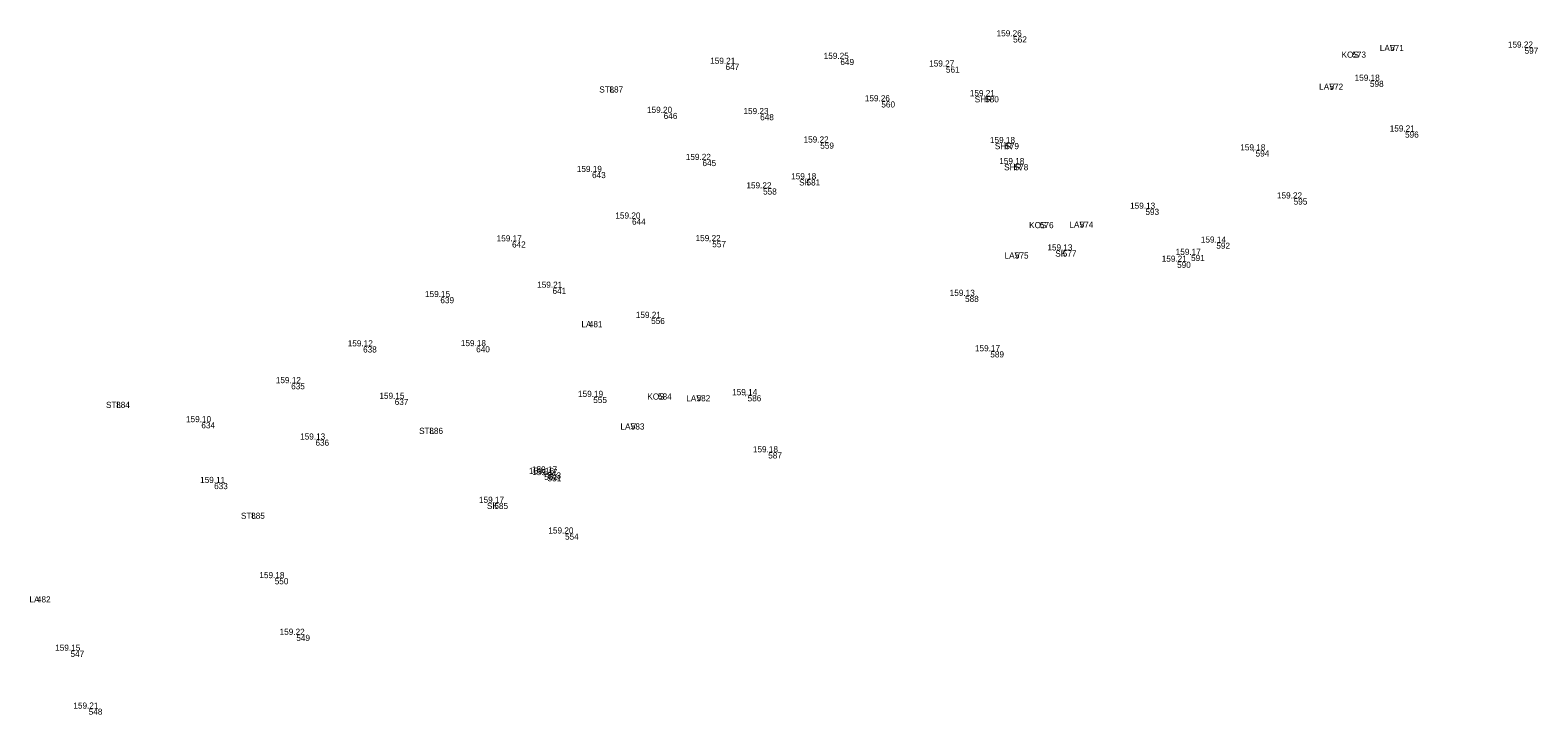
# Model space of a CAD drawing. Extents: x -583198 to -582878, y -1211024 to -1210637.
# Drawn here: x -582990.8 to -582929.4, y -1210859.4 to -1210831.4 of the extents above; entities that cross this region are included whole.
import ezdxf

# ---------------------------------------------------------------- set-up
doc = ezdxf.new("R2010")
doc.units = 0
for name, color, linetype in [('1   Kódy', 7, 'Continuous'), ('4   Body podrobné', 7, 'Continuous'), ('5   Body podrobné - čísla', 7, 'Continuous'), ('6   Body podrobné - výšky', 7, 'Continuous')]:
    doc.layers.add(name, color=color, linetype=linetype)

msp = doc.modelspace()

# ---------------------------------------------------------------- linework, layer by layer
at = {"layer": '4   Body podrobné'}
for p, q in [((-582950.84, -1210831.69), (-582950.839, -1210831.69)), ((-582957.88, -1210832.61), (-582957.879, -1210832.61)), ((-582937.02, -1210832.31), (-582937.019, -1210832.31)), ((-582935.48, -1210832.04), (-582935.479, -1210832.04)), ((-582930, -1210832.15), (-582929.999, -1210832.15)), ((-582962.56, -1210832.81), (-582962.559, -1210832.81)), ((-582953.58, -1210832.92), (-582953.579, -1210832.92)), ((-582967.29, -1210833.73), (-582967.289, -1210833.73)), ((-582937.95, -1210833.62), (-582937.949, -1210833.62)), ((-582936.3, -1210833.5), (-582936.299, -1210833.5)), ((-582956.21, -1210834.34), (-582956.209, -1210834.34)), ((-582951.98, -1210834.13), (-582951.979, -1210834.13)), ((-582965.08, -1210834.81), (-582965.079, -1210834.81)), ((-582961.15, -1210834.86), (-582961.149, -1210834.86)), ((-582934.87, -1210835.57), (-582934.869, -1210835.57)), ((-582958.7, -1210836.02), (-582958.699, -1210836.02)), ((-582951.16, -1210836.04), (-582951.159, -1210836.04)), ((-582963.5, -1210836.73), (-582963.499, -1210836.73)), ((-582950.78, -1210836.9), (-582950.779, -1210836.9)), ((-582940.96, -1210836.34), (-582940.959, -1210836.34)), ((-582968, -1210837.22), (-582967.999, -1210837.22)), ((-582959.26, -1210837.52), (-582959.259, -1210837.52)), ((-582961.03, -1210837.89), (-582961.029, -1210837.89)), ((-582945.45, -1210838.72), (-582945.449, -1210838.72)), ((-582939.41, -1210838.3), (-582939.409, -1210838.3)), ((-582966.37, -1210839.12), (-582966.369, -1210839.12)), ((-582949.75, -1210839.26), (-582949.749, -1210839.26)), ((-582948.13, -1210839.24), (-582948.129, -1210839.24)), ((-582971.26, -1210840.05), (-582971.259, -1210840.05)), ((-582963.1, -1210840.04), (-582963.099, -1210840.04)), ((-582950.77, -1210840.5), (-582950.769, -1210840.5)), ((-582948.82, -1210840.42), (-582948.819, -1210840.42)), ((-582943.59, -1210840.6), (-582943.589, -1210840.6)), ((-582942.56, -1210840.1), (-582942.559, -1210840.1)), ((-582944.16, -1210840.88), (-582944.159, -1210840.88)), ((-582974.18, -1210842.32), (-582974.179, -1210842.32)), ((-582969.61, -1210841.94), (-582969.609, -1210841.94)), ((-582952.8, -1210842.27), (-582952.799, -1210842.27)), ((-582968.13, -1210843.3), (-582968.129, -1210843.3)), ((-582965.59, -1210843.17), (-582965.589, -1210843.17)), ((-582977.33, -1210844.33), (-582977.329, -1210844.33)), ((-582972.72, -1210844.32), (-582972.719, -1210844.32)), ((-582951.77, -1210844.53), (-582951.769, -1210844.53)), ((-582980.26, -1210845.83), (-582980.259, -1210845.83)), ((-582987.39, -1210846.59), (-582987.389, -1210846.59)), ((-582976.04, -1210846.47), (-582976.039, -1210846.47)), ((-582967.95, -1210846.39), (-582967.949, -1210846.39)), ((-582965.31, -1210846.25), (-582965.309, -1210846.25)), ((-582963.74, -1210846.32), (-582963.739, -1210846.32)), ((-582961.66, -1210846.32), (-582961.659, -1210846.32)), ((-582983.92, -1210847.42), (-582983.919, -1210847.42)), ((-582974.63, -1210847.65), (-582974.629, -1210847.65)), ((-582966.42, -1210847.47), (-582966.419, -1210847.47)), ((-582979.27, -1210848.13), (-582979.269, -1210848.13)), ((-582960.82, -1210848.65), (-582960.819, -1210848.65)), ((-582969.95, -1210849.53), (-582969.949, -1210849.53)), ((-582969.82, -1210849.47), (-582969.819, -1210849.47)), ((-582969.81, -1210849.58), (-582969.809, -1210849.58)), ((-582983.4, -1210849.9), (-582983.399, -1210849.9)), ((-582971.98, -1210850.71), (-582971.979, -1210850.71)), ((-582981.89, -1210851.11), (-582981.889, -1210851.11)), ((-582969.1, -1210851.96), (-582969.099, -1210851.96)), ((-582980.93, -1210853.78), (-582980.929, -1210853.78)), ((-582990.62, -1210854.52), (-582990.619, -1210854.52)), ((-582980.05, -1210856.09), (-582980.049, -1210856.09)), ((-582989.25, -1210856.74), (-582989.249, -1210856.74)), ((-582988.51, -1210859.1), (-582988.509, -1210859.1))]:
    msp.add_line(p, q, dxfattribs=at)

# ---------------------------------------------------------------- texts
at = {"layer": '1   Kódy'}
for s, p in [('KOS', (-582937.365, -1210832.56)), ('LAV', (-582935.808, -1210832.29)), ('STL', (-582967.612, -1210833.98)), ('LAV', (-582938.278, -1210833.87)), ('SHR', (-582952.314, -1210834.38)), ('SHR', (-582951.494, -1210836.29)), ('SHR', (-582951.114, -1210837.15)), ('SK', (-582959.469, -1210837.77)), ('KOS', (-582950.095, -1210839.51)), ('LAV', (-582948.458, -1210839.49)), ('LAV', (-582951.098, -1210840.75)), ('SK', (-582949.029, -1210840.67)), ('LA', (-582968.34, -1210843.55)), ('STL', (-582987.712, -1210846.84)), ('KOS', (-582965.655, -1210846.5)), ('LAV', (-582964.068, -1210846.57)), ('STL', (-582974.952, -1210847.9)), ('LAV', (-582966.748, -1210847.72)), ('SK', (-582972.189, -1210850.96)), ('STL', (-582982.212, -1210851.36)), ('LA', (-582990.83, -1210854.77))]:
    msp.add_text(s, height=0.25, dxfattribs=at).set_placement(p)
at = {"layer": '5   Body podrobné - čísla'}
for s, p in [(' 562', (-582950.84, -1210831.94)), (' 649', (-582957.88, -1210832.86)), (' 573', (-582937.02, -1210832.56)), (' 571', (-582935.48, -1210832.29)), (' 597', (-582930, -1210832.4)), (' 647', (-582962.56, -1210833.06)), (' 561', (-582953.58, -1210833.17)), (' 887', (-582967.29, -1210833.98)), (' 572', (-582937.95, -1210833.87)), (' 598', (-582936.3, -1210833.75)), (' 560', (-582956.21, -1210834.59)), (' 580', (-582951.98, -1210834.38)), (' 646', (-582965.08, -1210835.06)), (' 648', (-582961.15, -1210835.11)), (' 596', (-582934.87, -1210835.82)), (' 559', (-582958.7, -1210836.27)), (' 579', (-582951.16, -1210836.29)), (' 645', (-582963.5, -1210836.98)), (' 578', (-582950.78, -1210837.15)), (' 594', (-582940.96, -1210836.59)), (' 643', (-582968, -1210837.47)), (' 581', (-582959.26, -1210837.77)), (' 558', (-582961.03, -1210838.14)), (' 593', (-582945.45, -1210838.97)), (' 595', (-582939.41, -1210838.55)), (' 644', (-582966.37, -1210839.37)), (' 576', (-582949.75, -1210839.51)), (' 574', (-582948.13, -1210839.49)), (' 642', (-582971.26, -1210840.3)), (' 557', (-582963.1, -1210840.29)), (' 575', (-582950.77, -1210840.75)), (' 577', (-582948.82, -1210840.67)), (' 591', (-582943.59, -1210840.85)), (' 592', (-582942.56, -1210840.35)), (' 590', (-582944.16, -1210841.13)), (' 639', (-582974.18, -1210842.57)), (' 641', (-582969.61, -1210842.19)), (' 588', (-582952.8, -1210842.52)), (' 481', (-582968.13, -1210843.55)), (' 556', (-582965.59, -1210843.42)), (' 640', (-582972.72, -1210844.57)), (' 638', (-582977.33, -1210844.58)), (' 589', (-582951.77, -1210844.78)), (' 635', (-582980.26, -1210846.08)), (' 884', (-582987.39, -1210846.84)), (' 637', (-582976.04, -1210846.72)), (' 555', (-582967.95, -1210846.64)), (' 584', (-582965.31, -1210846.5)), (' 582', (-582963.74, -1210846.57)), (' 586', (-582961.66, -1210846.57)), (' 634', (-582983.92, -1210847.67)), (' 886', (-582974.63, -1210847.9)), (' 583', (-582966.42, -1210847.72)), (' 636', (-582979.27, -1210848.38)), (' 587', (-582960.82, -1210848.9)), (' 552', (-582969.95, -1210849.78)), (' 553', (-582969.82, -1210849.72)), (' 551', (-582969.81, -1210849.83)), (' 633', (-582983.4, -1210850.15)), (' 585', (-582971.98, -1210850.96)), (' 885', (-582981.89, -1210851.36)), (' 554', (-582969.1, -1210852.21)), (' 550', (-582980.93, -1210854.03)), (' 482', (-582990.62, -1210854.77)), (' 549', (-582980.05, -1210856.34)), (' 547', (-582989.25, -1210856.99)), (' 548', (-582988.51, -1210859.35))]:
    msp.add_text(s, height=0.25, dxfattribs=at).set_placement(p)
at = {"layer": '6   Body podrobné - výšky'}
for s, p in [('159.26', (-582951.421, -1210831.69)), ('159.22', (-582930.587, -1210832.15)), ('159.21', (-582963.092, -1210832.81)), ('159.25', (-582958.467, -1210832.61)), ('159.27', (-582954.168, -1210832.92)), ('159.18', (-582936.832, -1210833.5)), ('159.26', (-582956.791, -1210834.34)), ('159.21', (-582952.512, -1210834.13)), ('159.20', (-582965.666, -1210834.81)), ('159.23', (-582961.737, -1210834.86)), ('159.21', (-582935.402, -1210835.57)), ('159.22', (-582959.287, -1210836.02)), ('159.18', (-582951.692, -1210836.04)), ('159.18', (-582941.492, -1210836.34)), ('159.22', (-582964.087, -1210836.73)), ('159.18', (-582951.312, -1210836.9)), ('159.19', (-582968.527, -1210837.22)), ('159.18', (-582959.792, -1210837.52)), ('159.22', (-582961.617, -1210837.89)), ('159.22', (-582939.997, -1210838.3)), ('159.13', (-582945.982, -1210838.72)), ('159.20', (-582966.956, -1210839.12)), ('159.17', (-582971.793, -1210840.05)), ('159.22', (-582963.687, -1210840.04)), ('159.14', (-582943.098, -1210840.1)), ('159.13', (-582949.352, -1210840.42)), ('159.21', (-582944.692, -1210840.88)), ('159.17', (-582944.123, -1210840.6)), ('159.21', (-582970.142, -1210841.94)), ('159.15', (-582974.712, -1210842.32)), ('159.13', (-582953.332, -1210842.27)), ('159.21', (-582966.122, -1210843.17)), ('159.12', (-582977.862, -1210844.33)), ('159.18', (-582973.252, -1210844.32)), ('159.17', (-582952.303, -1210844.53)), ('159.12', (-582980.792, -1210845.83)), ('159.19', (-582968.477, -1210846.39)), ('159.14', (-582962.198, -1210846.32)), ('159.15', (-582976.572, -1210846.47)), ('159.10', (-582984.451, -1210847.42)), ('159.13', (-582979.802, -1210848.13)), ('159.18', (-582961.352, -1210848.65)), ('159.17', (-582970.353, -1210849.47)), ('159.11', (-582983.878, -1210849.9)), ('159.16', (-582970.477, -1210849.53)), ('159.17', (-582970.343, -1210849.58)), ('159.17', (-582972.513, -1210850.71)), ('159.20', (-582969.686, -1210851.96)), ('159.18', (-582981.462, -1210853.78)), ('159.22', (-582980.637, -1210856.09)), ('159.15', (-582989.782, -1210856.74)), ('159.21', (-582989.042, -1210859.1))]:
    msp.add_text(s, height=0.25, dxfattribs=at).set_placement(p)

doc.saveas('drawing.dxf')
